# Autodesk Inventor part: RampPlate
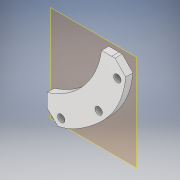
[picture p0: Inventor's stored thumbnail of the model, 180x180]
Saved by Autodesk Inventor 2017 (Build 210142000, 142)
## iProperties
Created: 2017-04
Part Number: RampPlate
Material: ABS Plastic
Document SubType Name: Modeling
Designer: 1460374
Density: 1.06 g/cm^3
Appearance: Smooth - White
Author: 1460374
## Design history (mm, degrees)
workplane "Work Plane1"
sketch "Sketch1"
  geometry: L1 (-38.276, -23.327)-(-38.276, -16.977); L2 (18.414, 41.452)-(12.064, 41.452); L3 (21.272, 41.452)-(30.642, 31.846) reference; L4 (21.272, 41.452)-(18.414, 41.452) reference; L5 (-38.276, -23.327)-(-38.276, -26.185) reference; L6 (-28.844, -35.157)-(-38.276, -26.185) reference; C1 r 3.225 at (7.037, -5.574) reference; C2 r 3.225 at (-25.835, -27.792) reference; C3 r 3.225 at (23.412, 27.176) reference; A1 r 71.128 centre (-58.386, 51.249) between (-38.276, -16.977) and (12.064, 41.452); 1 further point
  constraints: 4 end point, 2 point on circle, 1 centre point, 1 horizontal, 1 vertical
  dimensions: "d0" = 6.35 distance of L1.start L1.end; "d1" = 6.35 distance of L2.start L2.end
extrude "Extrusion1" new body sketch "Sketch1" distance "d2" = 6.35; taper "d3" = 0 deg
thicken "Thicken1" dims "d4" = 2.54, "d5" = 2.54
body "Solid1"
node "Reference2"
